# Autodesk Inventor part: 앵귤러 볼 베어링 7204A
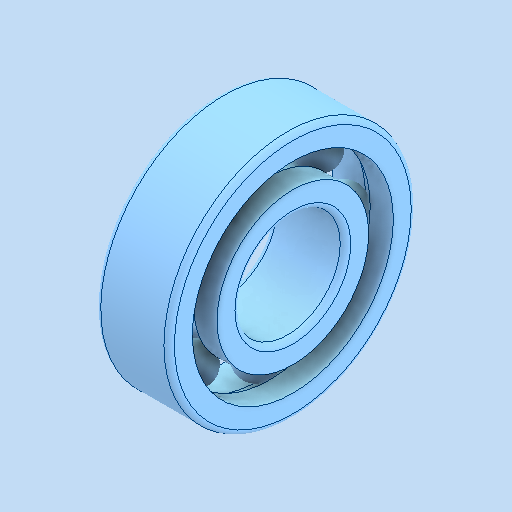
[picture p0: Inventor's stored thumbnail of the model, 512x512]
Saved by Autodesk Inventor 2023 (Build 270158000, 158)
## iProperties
Created: 2024-11
Part Number: 앵귤러 볼 베어링 7204A
Material: 강철, 연강
Description: 앵귤러 콘택트 볼 베어링
Document SubType Name: Modeling
Designer: asung
Density: 7.85 g/cm^3
Appearance: 기본값
Author: jhkim
Sending System: Autodesk Inventor 2025
Preprocessor: ST-DEVELOPER v20
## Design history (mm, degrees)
feature "Solid1"
feature "Solid1:1"
feature "Solid1:2"
feature "Solid1:3"
feature "Solid1:4"
feature "Solid1:5"
feature "Solid1:6"
feature "Solid1:7"
feature "Solid1:8"
feature "Solid1:9"
node "솔리드1"
node "솔리드2"
node "솔리드3"
node "솔리드4"
node "솔리드5"
node "솔리드6"
node "솔리드7"
node "솔리드8"
node "솔리드9"
node "솔리드10"
